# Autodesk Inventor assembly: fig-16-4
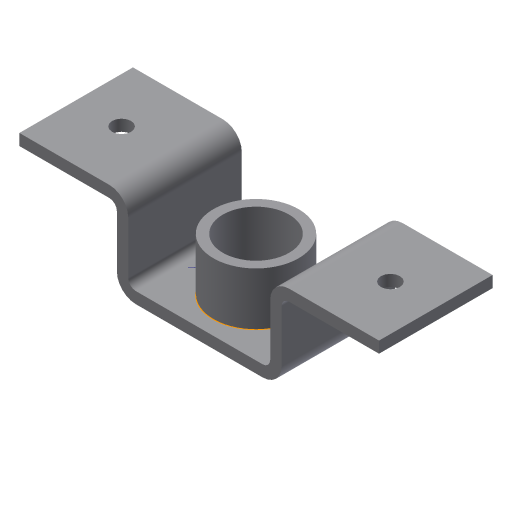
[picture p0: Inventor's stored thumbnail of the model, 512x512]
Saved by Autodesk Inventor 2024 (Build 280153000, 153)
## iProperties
Created: 2004-07
Part Number: fig-16-4
Document SubType Name: Weldment
Designer: CADCIM Technologies
Manufacturer: Standard
Standards Organization: Custom
Author: CADCIM Technologies
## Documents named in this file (3)
- D:\PROJECTS\Project 2023\RESOURCES INVENTOR 2024\RESOURCES INVENTOR 2024\Inventor_2023_Part\Inventor_2024_Part\c16_Inv_2024_prt\fig-16-4.iam
- D:\PROJECTS\Project 2023\RESOURCES INVENTOR 2024\RESOURCES INVENTOR 2024\Inventor_2023_Part\Inventor_2024_Part\c16_Inv_2024_prt\Bracket.ipt
- D:\PROJECTS\Project 2023\RESOURCES INVENTOR 2024\RESOURCES INVENTOR 2024\Inventor_2023_Part\Inventor_2024_Part\c16_Inv_2024_prt\cylinder.ipt
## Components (2 placed, 2 different names)
1. Bracket:1 — Insert:1
2. cylinder:1 — Insert:1
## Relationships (1: Insert 1)
- Insert:1: Bracket:1 ↔ cylinder:1
